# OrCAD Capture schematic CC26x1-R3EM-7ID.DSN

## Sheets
1 Mechanical: size A4; title: CC26x1-R3EM-7ID; rev: A0
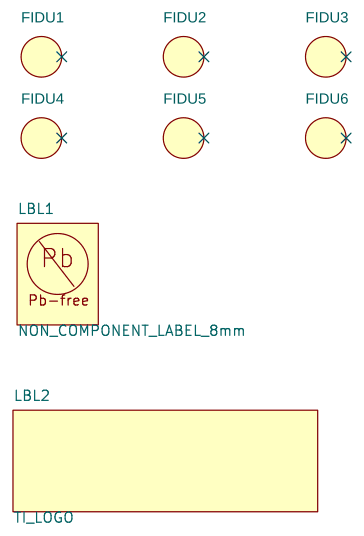
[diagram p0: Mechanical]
2 Revision
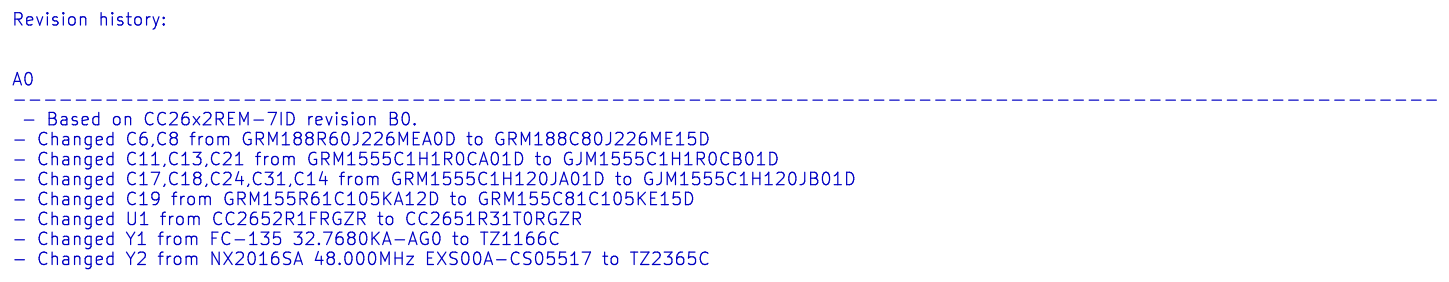
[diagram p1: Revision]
3 CC26x1-R3EM-7ID: size A3
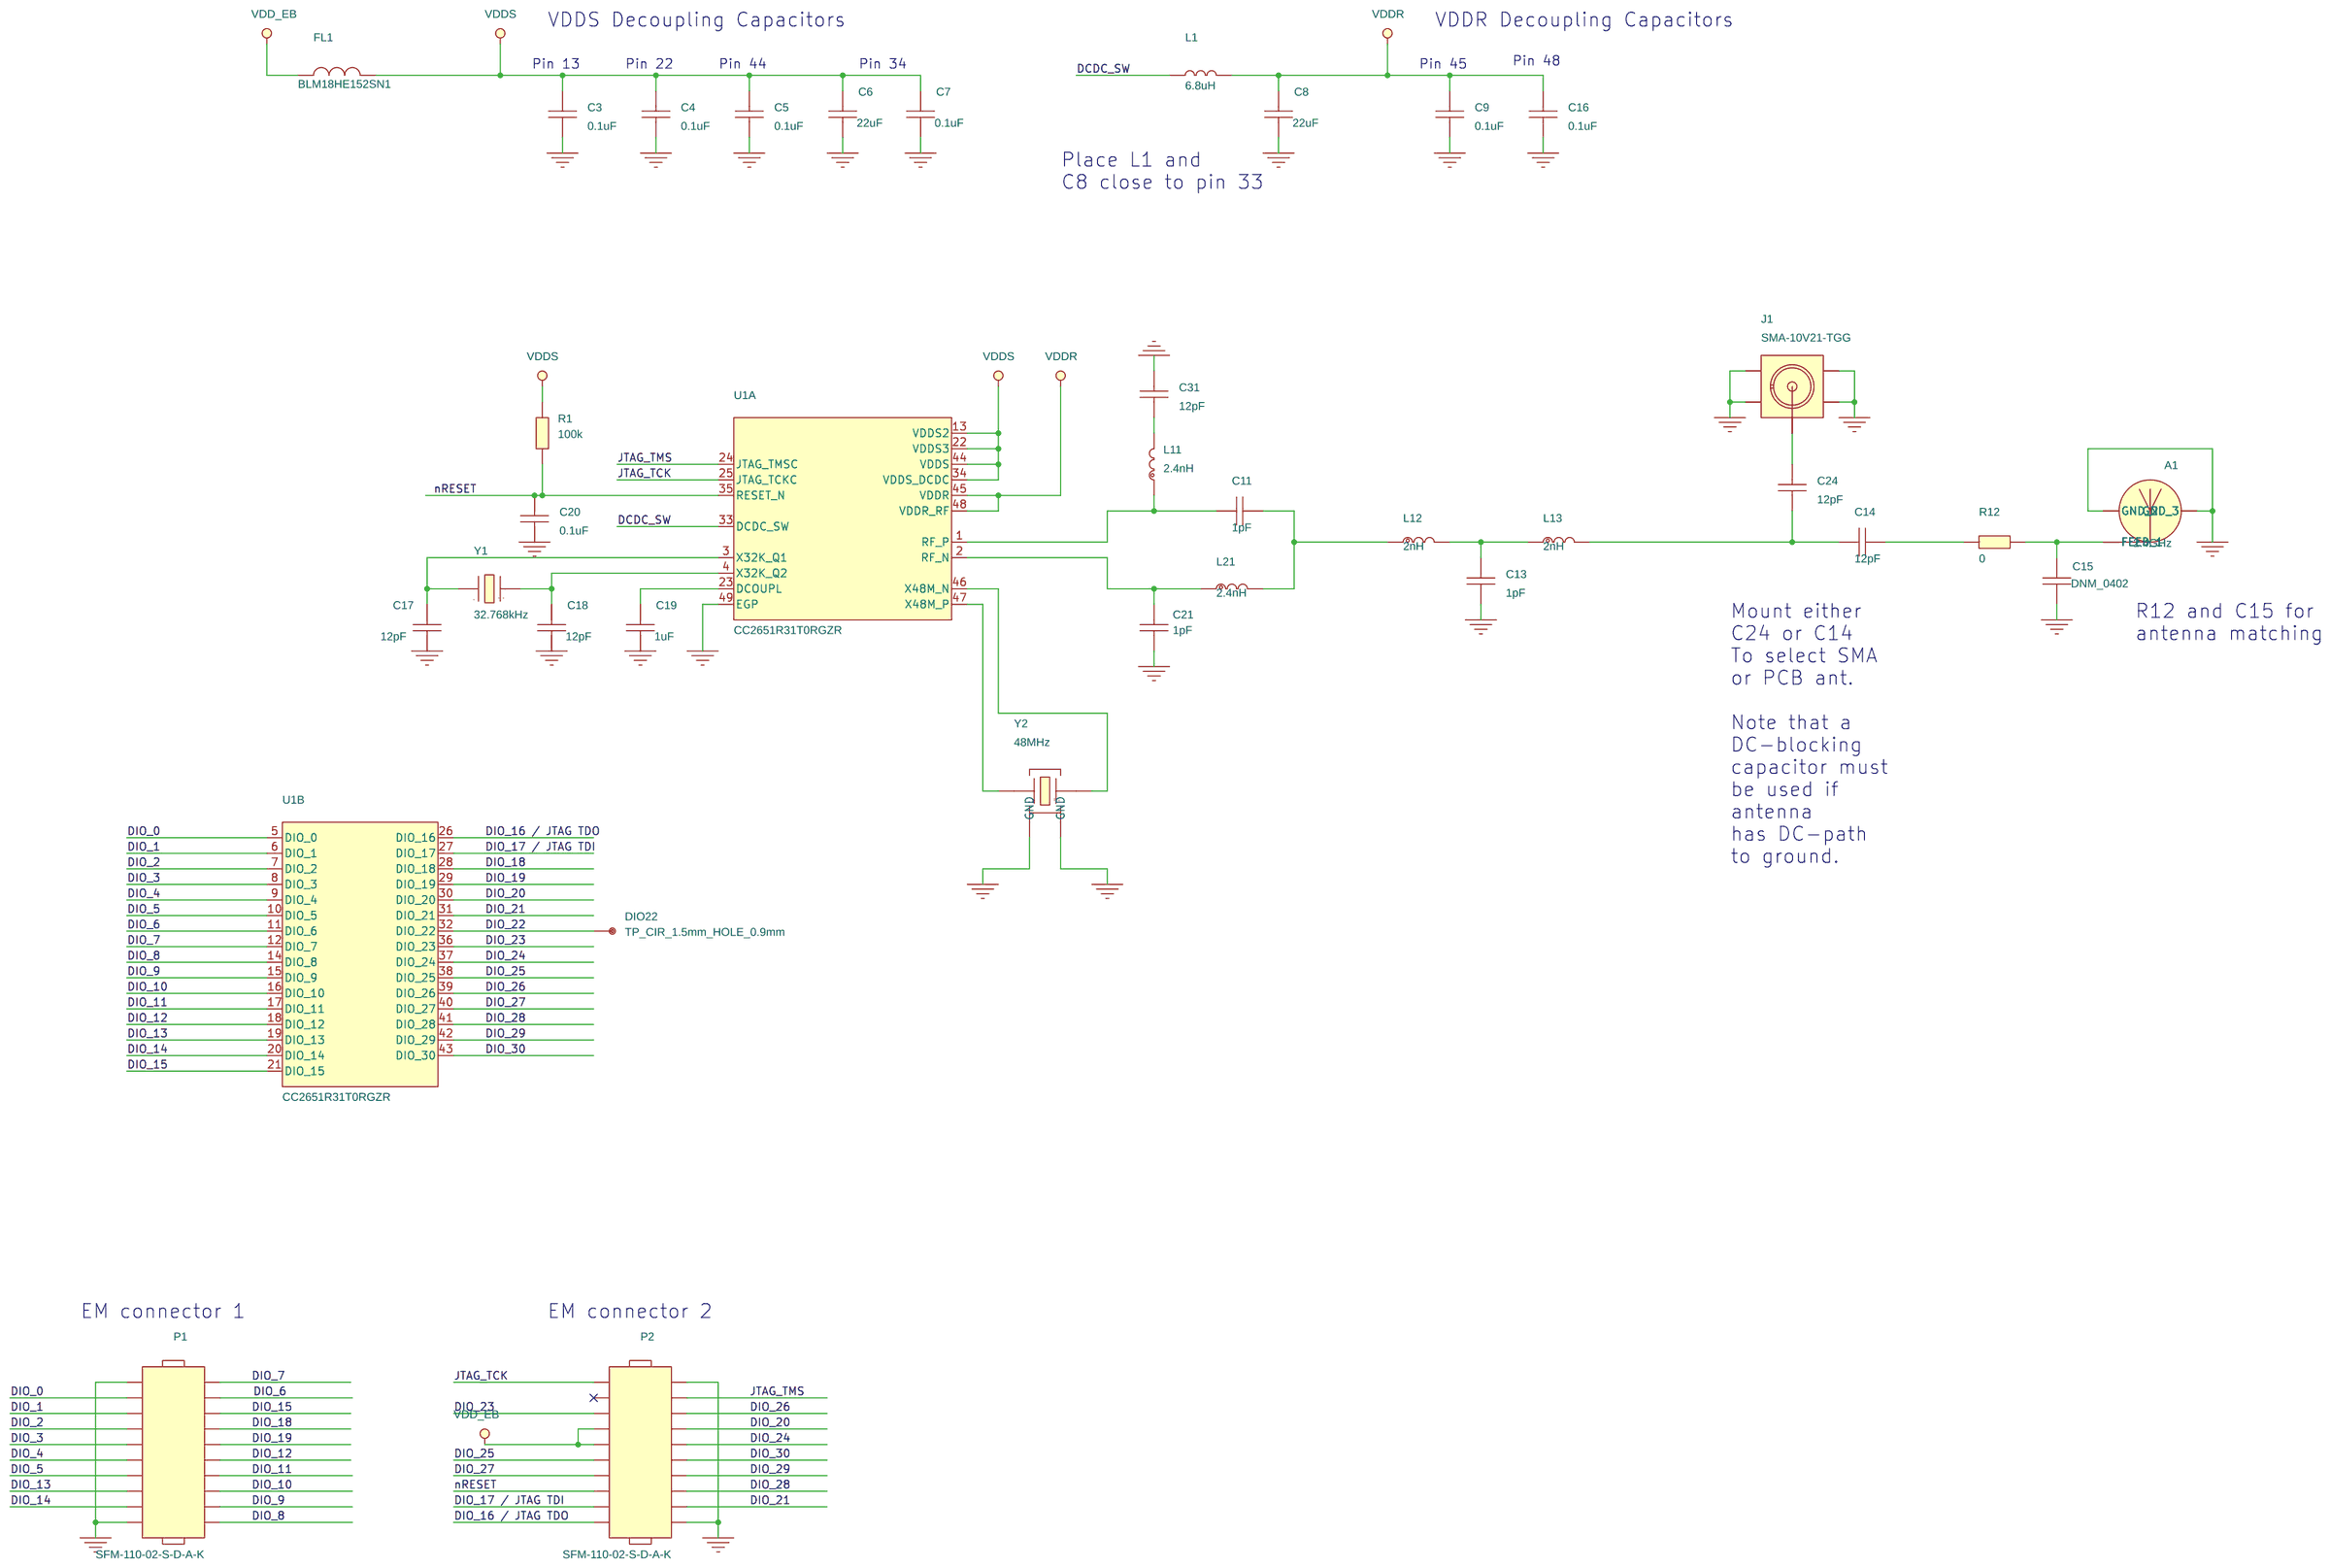
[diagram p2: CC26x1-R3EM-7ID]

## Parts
sheet CC26x1-R3EM-7ID
A1  2.4GHz  [ANTENNA_DN007AN]
C3  0.1uF  [CAPC1005X60B2N]
C4  0.1uF  [CAPC1005X60B2N]
C5  0.1uF  [CAPC1005X60B2N]
C6  22uF  [CAPC1608X100A2N]
C7  0.1uF  [CAPC1005X60B2N]
C8  22uF  [CAPC1608X100A2N]
C9  0.1uF  [CAPC1005X60B2N]
C11  1pF  [CAPC1005X60B2N]
C13  1pF  [CAPC1005X60B2N]
C14  12pF  [CAPC1005X60B2N]
C15  DNM_0402  [CAPC1005X60B2N]
C16  0.1uF  [CAPC1005X60B2N]
C17  12pF  [CAPC1005X60B2N]
C18  12pF  [CAPC1005X60B2N]
C19  1uF  [CAPC1005X60B2N]
C20  0.1uF  [CAPC1005X60B2N]
C21  1pF  [CAPC1005X60B2N]
C24  12pF  [CAPC1005X60B2N]
C31  12pF  [CAPC1005X60B2N]
DIO22  TP_CIR_1.5mm_HOLE_0.9mm  [TP150_90H]
FL1  BLM18HE152SN1  [FIL_BLM18HE152SN1DN]
J1  SMA-10V21-TGG  [HUSTSAN_SMA10V21TGGAN]
L1  6.8uH  [INDC2012X150A2N]
L11  2.4nH  [INDC1005X60D2N]
L12  2nH  [INDC1005X60D2N]
L13  2nH  [INDC1005X60D2N]
L21  2.4nH  [INDC1005X60D2N]
P1  SFM-110-02-S-D-A-K  [SAMTEC_SFM11002AN]
P2  SFM-110-02-S-D-A-K  [SAMTEC_SFM11002AN]
R1  100k  [RESC1005X40B2N]
R12  0  [RESC1005X40B2N]
U1  CC2651R31T0RGZR  [QFNFC50P700X700X100-49A2N]  (sections A,B)
Y1  32.768kHz  [XTAL_TZ1166C_A2N]
Y2  48MHz  [OSCCC200X160X50-4A2N]
sheet Mechanical
FIDU1  FIDU_1MM  [FID100X115B]
FIDU2  FIDU_1MM  [FID100X115B]
FIDU3  FIDU_1MM  [FID100X115B]
FIDU4  FIDU_1MM  [FID100X115B]
FIDU5  FIDU_1MM  [FID100X115B]
FIDU6  FIDU_1MM  [FID100X115B]
LBL1  NON_COMPONENT_LABEL_8mm  [LABEL_PB-FREE_8MM_A2N]
LBL2  TI_LOGO  [TI_LOGO_1]

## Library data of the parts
A1 = ANTENNA_DN007: ANTENNA, NON COMPONENT, 2.4GHz INVERTED F ANTENNA, NOT APPLY; Additional Datasheet URL: N/A; AutoDoc File: https://notefied-dynamic-precision.com/DB/Apps/Desktop/Item/Object.aspx?id=85542; BU Name: DYNAMIC PRECISION GDANSK; Budget Currency: N/A; Budget Price: N/A; CLASS: DISCRETE; Client Status: UNDER_REVIEW; Country of Origin: Missing Info; Datasheet URL: www.ti.com; Datasheet URL 1: http://www.ti.com/lit/an/swru120b/swru120b.pdf; Datasheet URL 2: N/A; Definied Quality: INDUSTRIAL; Esd Level: HBM 500V; Exclusive for Customers: TEXAS INSTRUMENTS NORWAY; FPLIST: ANTENNA_DN007N,ANTENNA_DN007AN,; MPN: DN007; MPN Status: ACTIVE; MSL: N/A; MTBF: N/A; MTBF Standard: N/A; Manufacturer: TEXAS INSTRUMENTS; Mass: N/A; Max Oper Temp: +85DEGC; Maximum Operating Temperature: +85DEGC; Min Oper Temp: -40DEGC; Minimum Operating Temperature: -40DEGC; Mounting Type: Not Apply; NOTE Status: PREFERRED; NOTEfied URL: https://notefied-dynamic-precision.com/NOTEfiedWebInterface/part/show?partNumber=13-00347; Notes: Custom Item; Old Footprint: ANTENNA_DN007N,ANTENNA_DN007AN; Packing Size: N/A; Packing Type: Missing Info; Part Number: 13-00347; Part Type: Mechanic|ANTENNA|NON COMPONENT; ROHS: Not Applicable; Revision: R019; RoHS Status: NOT_APPLICABLE; Status: Released; Texas Part Status: Under Review; Type: Mechanic; Vendor: TEXAS INSTRUMENTS; Vendor Part Number: DN007; Vendor Part Status: Active; WEIGHT: N/A
C3-C5 C9 C16 C20 = CAPACITOR: CAPACITOR, CERAMIC X7R, 0.1uF, 25V, -10%/+10%, -55DEGC/+125DEGC, 0402, SMD; Additional Datasheet URL: https://search.murata.co.jp/Ceramy/image/img/A01X/G101/ENG/GRM155R71E104KE14-01A.pdf; AutoDoc File: https://notefied-dynamic-precision.com/DB/Apps/Desktop/Item/Object.aspx?id=115293; BU Name: TEXAS INSTRUMENTS NORWAY; Client Status: UNDER_REVIEW; Datasheet URL: https://www.murata.com/~/media/webrenewal/support/library/catalog/products/capacitor/mlcc/c02e.ashx?la=en-gb; Datasheet URL 1: http://psearch.murata.com/capacitor/product/GRM155R71E104KE14%23.pdf; Datasheet URL 2: N/A; Dielectric Type: X7R; LifeCycle Status: ACTIVE; MPN: GRM155R70J104KA01D; MPN Status: ACTIVE; Manufacturer: MURATA; Mass: 0.0016g; Max Oper Temp: +125DEGC; Max Tol: +10%; Maximum Operating Temperature: +125DEGC; Maximum Tolerance: +10%; Min Oper Temp: -55DEGC; Min Tol: -10%; Minimum Operating Temperature: -55DEGC; Minimum Tolerance: -10%; Mounting Type: SMD; NOTE Status: PREFERRED; NOTEfied URL: https://notefied-dynamic-precision.com/NOTEfiedWebInterface/part/show?partNumber=02-07861; Old Footprint: CAPC1005X60N,0402; PCB Package: 0402; Packing Size: 10000; Packing Type: Tape & Reel; Part Number: 02-07861; Part Type: Capacitor|CERAMIC|0402|STANDARD; REACH/SVHC Compliance: Compliant; REACH/SVHC Details: SVHC List Version Jul 7, 2017; REACH/SVHC Source: REACH Declaration; REACH/SVHC Status: Unaffected; REACH/SVHC_COMPLIANCE: COMPLIANT; REACH/SVHC_DETAILS: SVHC LIST VERSION Jun 20, 2016; REACH/SVHC_SOURCE: REACH DECLARATION; REACH/SVHC_STATUS: UNAFFECTED; ROHS: Compliant; Rated Voltage: 25V; Revision: R014; RoHS Status: ROHS_COMPLIANT; Rtd Voltage: 25V; Status: Released; Texas Part Status: Under Review; Type: Capacitor; Vendor: MURATA; Vendor Part Number: GRM155R71E104KE14D; Vendor Part Status: NRND; WEIGHT: 0.0016g
C6 C8 = CAPACITOR: CAPACITOR, CERAMIC X6S, 22uF, 6.3V, -20%/+20%, -55DEGC/+105DEGC, 0603, SMD; ALT_SYMBOLS: CAPC1608X100A2L,CAPC1608X100A2M; Additional Datasheet URL: https://search.murata.co.jp/Ceramy/image/img/A01X/G101/ENG/GRM188C80J226ME15-02A.pdf; AutoDoc File: https://notefied-dynamic-precision.com/DB/Apps/Desktop/Item/Object.aspx?id=104385; BU Name: DYNAMIC PRECISION GDANSK; Budget Currency: EUR; Budget Price: 0.062; Budgetary Price: 0.07648 USD; Client Status: UNDER_REVIEW; Datasheet URL: https://www.murata.com/-/media/webrenewal/support/library/catalog/products/capacitor/mlcc/c02e.ashx; Datasheet URL 1: http://psearch.murata.com/capacitor/product/GRM188R60J226MEA0%23.pdf; Datasheet URL 2: N/A; Definied Quality: INDUSTRIAL; Dielectric Type: X6S; Esd Level: N/A; Lead Time: 15; MPN: GRM188R60J106ME47D; MPN Status: NRND; MSL: 1; MTBF: N/A; MTBF Standard: N/A; Manufacturer: MURATA; Mass: 0.0091g; Max Oper Temp: +85DEGC; Max Tol: +20%; Maximum Operating Temperature: +105DEGC; Maximum Tolerance: +20%; Min Oper Temp: -55DEGC; Min Tol: -20%; Minimum Operating Temperature: -55DEGC; Minimum Tolerance: -20%; Mounting Type: SMD; NOTE Status: PREFERRED; NOTEfied URL: https://notefied-dynamic-precision.com/NOTEfiedWebInterface/part/show?partNumber=02-09737; Old Footprint: CAPC1608X90N; PCB Package: 0603; Packing Size: 4000; Packing Type: Tape & Reel; Part Number: 02-09737; Part Type: Capacitor|CERAMIC|0603|STANDARD; REACH/SVHC Compliance: Compliant; REACH/SVHC Details: SVHC List Version Jan 16, 2020; REACH/SVHC Source: REACH Declaration; REACH/SVHC Status: Unaffected; REACH/SVHC_COMPLIANCE: COMPLIANT; REACH/SVHC_DETAILS: SVHC LIST VERSION Dec 17, 2015; REACH/SVHC_SOURCE: REACH DECLARATION; REACH/SVHC_STATUS: UNAFFECTED; ROHS: Compliant; Rated Current: N/A; Rated Voltage: 6.3V; Revision: R001; RoHS Status: ROHS_COMPLIANT; Rtd Voltage: 6.3V; Status: Released; Texas Part Status: Under Review; Type: Capacitor; Vendor: MURATA; Vendor Part Number: GRM188C80J226ME15D; Vendor Part Status: Active; WEIGHT: 0.0091g
C7 = CAPACITOR: CAPACITOR, CERAMIC X7R, 0.1uF, 25V, -10%/+10%, -55DEGC/+125DEGC, 0402, SMD; Additional Datasheet URL: https://search.murata.co.jp/Ceramy/image/img/A01X/G101/ENG/GRM155R71E104KE14-01A.pdf; AutoDoc File: https://notefied-dynamic-precision.com/DB/Apps/Desktop/Item/Object.aspx?id=115293; BU Name: TEXAS INSTRUMENTS NORWAY; Cage Code: C0151; Client Status: UNDER_REVIEW; Datasheet URL: https://www.murata.com/~/media/webrenewal/support/library/catalog/products/capacitor/mlcc/c02e.ashx?la=en-gb; Datasheet URL 1: http://psearch.murata.com/capacitor/product/GRM155R71E104KE14%23.pdf; Datasheet URL 2: N/A; Dielectric Type: X7R; MPN: GRM188R71E104KA01D; MPN Status: ACTIVE; Manufacturer: MURATA; Mass: 0.0016g; Max Oper Temp: +125DEGC; Max Tol: +10%; Maximum Operating Temperature: +125DEGC; Maximum Tolerance: +10%; Min Oper Temp: -55DEGC; Min Tol: -10%; Minimum Operating Temperature: -55DEGC; Minimum Tolerance: -10%; Mounting Type: SMD; NOTE Status: PREFERRED; NOTEfied URL: https://notefied-dynamic-precision.com/NOTEfiedWebInterface/part/show?partNumber=02-07861; Old Footprint: CAPC1608X90N,0603; PCB Package: 0402; Packing Size: 10000; Packing Type: Tape & Reel; Part Number: 02-07861; Part Type: Capacitor|CERAMIC|0402|STANDARD; REACH/SVHC Compliance: Compliant; REACH/SVHC Details: SVHC List Version Jul 7, 2017; REACH/SVHC Source: REACH Declaration; REACH/SVHC Status: Unaffected; REACH/SVHC_COMPLIANCE: COMPLIANT; REACH/SVHC_DETAILS: SVHC LIST VERSION Jun 20, 2016; REACH/SVHC_SOURCE: REACH DECLARATION; REACH/SVHC_STATUS: UNAFFECTED; ROHS: Compliant; Rated Voltage: 25V; Revision: R014; RoHS Status: ROHS_COMPLIANT; Rtd Voltage: 25V; Status: Released; Texas Part Status: Under Review; Type: Capacitor; Vendor: MURATA; Vendor Part Number: GRM155R71E104KE14D; Vendor Part Status: NRND; WEIGHT: 0.0016g
C11 C13 C21 = CAPACITOR: CAPACITOR, CERAMIC C0G/NP0, 1pF, 50V, -0.25pF/+0.25pF, -55DEGC/+125DEGC, 0402, SMD; Additional Datasheet URL: https://search.murata.co.jp/Ceramy/image/img/A01X/G101/ENG/GJM1555C1H1R0CB01-01.pdf; AutoDoc File: https://notefied-dynamic-precision.com/DB/Apps/Desktop/Item/Object.aspx?id=113355; BU Name: TEXAS INSTRUMENTS NORWAY; Budget Currency: EUR; Budget Price: 0.006; Datasheet URL: https://www.murata.com/-/media/webrenewal/support/library/catalog/products/capacitor/mlcc/c02e.ashx; Datasheet URL 1: http://psearch.murata.com/capacitor/product/GRM1555C1H1R0CA01%23.pdf; Datasheet URL 2: http://search.murata.co.jp/Ceramy/image/img/w_hinm/L0005E.pdf; Dielectric Type: C0G/NP0; MPN: GRM1555C1H1R0CA01D; MPN Status: ACTIVE; Manufacturer: MURATA; Mass: 0.0016g; Max Oper Temp: +125DEGC; Max Tol: +0.25pF; Maximum Operating Temperature: +125DEGC; Maximum Tolerance: +0.25pF; Min Oper Temp: -55DEGC; Min Tol: -0.25pF; Minimum Operating Temperature: -55DEGC; Minimum Tolerance: -0.25pF; Mounting Type: SMD; NOTE Status: PREFERRED; NOTEfied URL: https://notefied-dynamic-precision.com/NOTEfiedWebInterface/part/show?partNumber=02-09706; Old Footprint: CAPC1005X60N; PCB Package: 0402; Packing Size: 10000; Packing Type: Tape & Reel; Part Number: 02-09706; Part Type: Capacitor|CERAMIC|0402|STANDARD; REACH/SVHC Compliance: Compliant; REACH/SVHC Details: SVHC List Version Jan 16, 2020; REACH/SVHC Source: REACH Declaration; REACH/SVHC Status: Unaffected; REACH/SVHC_COMPLIANCE: COMPLIANT; REACH/SVHC_DETAILS: SVHC LIST VERSION Dec 17, 2015; REACH/SVHC_SOURCE: REACH DECLARATION; REACH/SVHC_STATUS: UNAFFECTED; ROHS: Compliant; Rated Voltage: 50V; Revision: R002; RoHS Status: ROHS_COMPLIANT; Rtd Voltage: 50V; Status: Released; Texas Part Status: Under Review; Type: Capacitor; Vendor: MURATA; Vendor Part Number: GJM1555C1H1R0CB01D; Vendor Part Status: Active; WEIGHT: 0.0016g
C14 C24 = CAPACITOR: CAPACITOR, CERAMIC C0G/NP0, 12pF, 50V, -5%/+5%, -55DEGC/+125DEGC, 0402, SMD; Additional Datasheet URL: https://search.murata.co.jp/Ceramy/image/img/A01X/G101/ENG/GJM1555C1H120JB01-01.pdf; AutoDoc File: https://notefied-dynamic-precision.com/DB/Apps/Desktop/Item/Object.aspx?id=113345; BU Name: TEXAS INSTRUMENTS NORWAY; Budget Currency: EUR; Budget Price: 0.007; Datasheet URL: https://www.murata.com/-/media/webrenewal/support/library/catalog/products/capacitor/mlcc/c02e.ashx; Datasheet URL 1: http://psearch.murata.com/capacitor/product/GRM1555C1H120JA01%23.pdf; Datasheet URL 2: http://search.murata.co.jp/Ceramy/image/img/w_hinm/L0005E.pdf; Dielectric Type: C0G/NP0; MPN: GRM1555C1H120JA01D; MPN Status: ACTIVE; Manufacturer: MURATA; Mass: 0.0016g; Max Oper Temp: +125DEGC; Max Tol: +5%; Maximum Operating Temperature: +125DEGC; Maximum Tolerance: +5%; Min Oper Temp: -55DEGC; Min Tol: -5%; Minimum Operating Temperature: -55DEGC; Minimum Tolerance: -5%; Mounting Type: SMD; NOTE Status: PREFERRED; NOTEfied URL: https://notefied-dynamic-precision.com/NOTEfiedWebInterface/part/show?partNumber=02-09704; Old Footprint: CAPC1005X60N; PCB Package: 0402; Packing Size: 10000; Packing Type: Tape & Reel; Part Number: 02-09704; Part Type: Capacitor|CERAMIC|0402|STANDARD; REACH/SVHC Compliance: Compliant; REACH/SVHC Details: SVHC List Version Jan 16, 2020; REACH/SVHC Source: REACH Declaration; REACH/SVHC Status: Unaffected; REACH/SVHC_COMPLIANCE: COMPLIANT; REACH/SVHC_DETAILS: SVHC LIST VERSION Dec 17, 2015; REACH/SVHC_SOURCE: REACH DECLARATION; REACH/SVHC_STATUS: UNAFFECTED; ROHS: Compliant; Rated Voltage: 50V; Revision: R002; RoHS Status: ROHS_COMPLIANT; Rtd Voltage: 50V; Status: Released; Texas Part Status: Under Review; Type: Capacitor; Vendor: MURATA; Vendor Part Number: GJM1555C1H120JB01D; Vendor Part Status: Active; WEIGHT: 0.0016g
C15 = CAPACITOR: CAPACITOR, CERAMIC, TBD, 0402, SMD, DNM; Additional Datasheet URL: N/A; AutoDoc File: https://notefied-dynamic-precision.com/DB/Apps/Desktop/Item/Object.aspx?id=113344; BU Name: TEXAS INSTRUMENTS NORWAY; Country of Origin: Missing Info; Datasheet URL: N/A; Datasheet URL 1: N/A; Datasheet URL 2: N/A; Dielectric Type: MISSING-INFO; Exclusive for Customers: TEXAS INSTRUMENTS NORWAY; MPN: CAPACITOR_0402_DNM_N/A_M; MPN Status: ACTIVE; Manufacturer: Manufacturer selection; Mass: N/A; Max Oper Temp: +125DEGC; Maximum Operating Temperature: +125DEGC; Min Oper Temp: -55DEGC; Minimum Operating Temperature: -55DEGC; Mounting Type: SMD; NOTE Status: PREFERRED; NOTEfied URL: https://notefied-dynamic-precision.com/NOTEfiedWebInterface/part/show?partNumber=02-07616; Notes: Standard item: Duplicate Reason: custom footprint for TEXAS INSTRUMENTS NORWAY.; Old Footprint: CAPC1005X60N; PCB Package: 0402; Part Number: 02-07616; Part Type: Capacitor|CERAMIC|0402|STANDARD; ROHS: Compliant; Revision: R014; RoHS Status: ROHS_COMPLIANT; Status: Released; Texas Part Status: Under Review; Type: Capacitor; Vendor: MANUFACTURER SELECTION; Vendor Part Number: CAPACITOR_TBD_0402_DNM; Vendor Part Status: Active; Weight: N/A
C17 C18 = CAPACITOR: CAPACITOR, CERAMIC C0G/NP0, 12pF, 50V, -5%/+5%, -55DEGC/+125DEGC, 0402, SMD; Additional Datasheet URL: https://search.murata.co.jp/Ceramy/image/img/A01X/G101/ENG/GJM1555C1H120JB01-01.pdf; AutoDoc File: https://notefied-dynamic-precision.com/DB/Apps/Desktop/Item/Object.aspx?id=113345; BU Name: TEXAS INSTRUMENTS NORWAY; Budget Currency: EUR; Budget Price: 0.007; Datasheet URL: https://www.murata.com/-/media/webrenewal/support/library/catalog/products/capacitor/mlcc/c02e.ashx; Datasheet URL 1: http://psearch.murata.com/capacitor/product/GRM1555C1H120JA01%23.pdf; Datasheet URL 2: http://search.murata.co.jp/Ceramy/image/img/w_hinm/L0005E.pdf; Definied Quality: INDUSTRIAL; Dielectric Type: C0G/NP0; Esd Level: N/A; LifeCycle Status: ACTIVE; MPN: CAPACITOR_0402_12pF_C0G/NP0_M_+/-5%_50V; MPN Status: ACTIVE; MSL: N/A; MTBF: N/A; MTBF Standard: N/A; Manufacturer: MANUFACTURER SELECTION; Mass: 0.0016g; Max Oper Temp: +125DEGC; Max Tol: +5%; Maximum Operating Temperature: +125DEGC; Maximum Tolerance: +5%; Min Oper Temp: -55DEGC; Min Tol: -5%; Minimum Operating Temperature: -55DEGC; Minimum Tolerance: -5%; Mounting Type: SMD; NOTE Status: PREFERRED; NOTEfied URL: https://notefied-dynamic-precision.com/NOTEfiedWebInterface/part/show?partNumber=02-09704; Old Footprint: CAPC1005X60N; PCB Package: 0402; Packing Size: 10000; Packing Type: Tape & Reel; Part Number: 02-09704; Part Type: Capacitor|CERAMIC|0402|STANDARD; REACH/SVHC Compliance: Compliant; REACH/SVHC Details: SVHC List Version Jan 16, 2020; REACH/SVHC Source: REACH Declaration; REACH/SVHC Status: Unaffected; REACH/SVHC_COMPLIANCE: COMPLIANT; REACH/SVHC_DETAILS: SVHC LIST VERSION Dec 17, 2015; REACH/SVHC_SOURCE: REACH DECLARATION; REACH/SVHC_STATUS: UNAFFECTED; ROHS: Compliant; Rated Voltage: 50V; Revision: R002; RoHS Status: ROHS_COMPLIANT; Rtd Voltage: 50V; Status: Released; Texas Part Status: Under Review; Type: Capacitor; Vendor: MURATA; Vendor Part Number: GJM1555C1H120JB01D; Vendor Part Status: Active; WEIGHT: 0.0016g
C19 = CAPACITOR: CAPACITOR, CERAMIC X6S, 1uF, 16V, -10%/+10%, -55DEGC/+105DEGC, 0402, SMD; Additional Datasheet URL: https://search.murata.co.jp/Ceramy/image/img/A01X/G101/ENG/GRM155C81C105KE15-01A.pdf; AutoDoc File: https://notefied-dynamic-precision.com/DB/Apps/Desktop/Item/Object.aspx?id=115295; BU Name: TEXAS INSTRUMENTS NORWAY; Client Status: UNDER_REVIEW; Datasheet URL: https://www.murata.com/-/media/webrenewal/support/library/catalog/products/capacitor/mlcc/c02e.ashx; Datasheet URL 1: http://psearch.murata.com/capacitor/product/GRM155R61C105KA12%23.pdf; Datasheet URL 2: N/A; Definied Quality: INDUSTRIAL; Dielectric Type: X6S; Esd Level: N/A; MPN: GRM155R61A105KE15D; MPN Status: ACTIVE; MSL: 1; MTBF: N/A; MTBF Standard: N/A; Manufacturer: MURATA; Mass: 0.0016g; Max Oper Temp: +85DEGC; Max Tol: +10%; Maximum Operating Temperature: +105DEGC; Maximum Tolerance: +10%; Min Oper Temp: -55DEGC; Min Tol: -10%; Minimum Operating Temperature: -55DEGC; Minimum Tolerance: -10%; Mounting Type: SMD; NOTE Status: PREFERRED; NOTEfied URL: https://notefied-dynamic-precision.com/NOTEfiedWebInterface/part/show?partNumber=02-09721; Old Footprint: CAPC1005X60N,0402; PCB Package: 0402; Packing Size: 10000; Packing Type: Tape & Reel; Part Number: 02-09721; Part Type: Capacitor|CERAMIC|0402|STANDARD; REACH/SVHC Compliance: Compliant; REACH/SVHC Details: SVHC List Version Jan 16, 2020; REACH/SVHC Source: REACH Declaration; REACH/SVHC Status: Unaffected; REACH/SVHC_COMPLIANCE: COMPLIANT; REACH/SVHC_DETAILS: SVHC LIST VERSION Jun 20, 2016; REACH/SVHC_SOURCE: REACH DECLARATION; REACH/SVHC_STATUS: UNAFFECTED; ROHS: Compliant; Rated Voltage: 16V; Revision: R002; RoHS Status: ROHS_COMPLIANT; Rtd Voltage: 16V; Status: Released; Texas Part Status: Under Review; Type: Capacitor; Vendor: MURATA; Vendor Part Number: GRM155C81C105KE15D; Vendor Part Status: Active; WEIGHT: 0.0016g
C31 = CAPACITOR: CAPACITOR, CERAMIC C0G/NP0, 12pF, 50V, -5%/+5%, -55DEGC/+125DEGC, 0402, SMD; Additional Datasheet URL: https://search.murata.co.jp/Ceramy/image/img/A01X/G101/ENG/GJM1555C1H120JB01-01.pdf; AutoDoc File: https://notefied-dynamic-precision.com/DB/Apps/Desktop/Item/Object.aspx?id=113345; BU Name: TEXAS INSTRUMENTS NORWAY; Budget Currency: EUR; Budget Price: 0.007; Datasheet URL: https://www.murata.com/-/media/webrenewal/support/library/catalog/products/capacitor/mlcc/c02e.ashx; Datasheet URL 1: http://psearch.murata.com/capacitor/product/GRM1555C1H120JA01%23.pdf; Datasheet URL 2: http://search.murata.co.jp/Ceramy/image/img/w_hinm/L0005E.pdf; Dielectric Type: C0G/NP0; MPN: GRM1555C1H6R8CA01D; MPN Status: ACTIVE; Manufacturer: MURATA; Mass: 0.0016g; Max Oper Temp: +125DEGC; Max Tol: +5%; Maximum Operating Temperature: +125DEGC; Maximum Tolerance: +5%; Min Oper Temp: -55DEGC; Min Tol: -5%; Minimum Operating Temperature: -55DEGC; Minimum Tolerance: -5%; Mounting Type: SMD; NOTE Status: PREFERRED; NOTEfied URL: https://notefied-dynamic-precision.com/NOTEfiedWebInterface/part/show?partNumber=02-09704; Old Footprint: CAPC1005X60N; PCB Package: 0402; Packing Size: 10000; Packing Type: Tape & Reel; Part Number: 02-09704; Part Type: Capacitor|CERAMIC|0402|STANDARD; REACH/SVHC Compliance: Compliant; REACH/SVHC Details: SVHC List Version Jan 16, 2020; REACH/SVHC Source: REACH Declaration; REACH/SVHC Status: Unaffected; REACH/SVHC_COMPLIANCE: COMPLIANT; REACH/SVHC_DETAILS: SVHC LIST VERSION Dec 17, 2015; REACH/SVHC_SOURCE: REACH DECLARATION; REACH/SVHC_STATUS: UNAFFECTED; ROHS: Compliant; Rated Voltage: 50V; Revision: R002; RoHS Status: ROHS_COMPLIANT; Rtd Voltage: 50V; Status: Released; Texas Part Status: Under Review; Type: Capacitor; Vendor: MURATA; Vendor Part Number: GJM1555C1H120JB01D; Vendor Part Status: Active; WEIGHT: 0.0016g
DIO22 = TEST_POINT: NON COMPONENT, TEST POINT, CIRCULAR 1.5mm, HOLE 0.9mm, PTH; Additional Datasheet URL: N/A; AutoDoc File: https://notefied-dynamic-precision.com/DB/Apps/Desktop/Item/Object.aspx?id=84966; BU Name: DYNAMIC PRECISION GDANSK; CLASS: IO; Country of Origin: Missing Info; Datasheet URL: N/A; FPLIST: TP150_90H,; Mass: N/A; Mounting Type: PTH; NOTEfied URL: https://notefied-dynamic-precision.com/NOTEfiedWebInterface/part/show?partNumber=19-00299; Packing Size: N/A; Packing Type: Missing Info; Part Number: 19-00299; Part Type: Non Component|TEST POINT; ROHS: Not Applicable; Revision: R018; Status: Released; Texas Part Status: Under Review; Type: Non Component; Vendor: NON_COMPONENT; Vendor Part Status: Active
FL1 = FILTER_2PIN: FILTER, EMI, FERRITE BEAD, 1500@100MHz, -25%/+25%, -55DEGC/+125DEGC, 0603, SMD; ALT_SYMBOLS: FIL_BLM18HE152SN1DL,FIL_BLM18HE152SN1DM; Additional Datasheet URL: https://www.murata.com/en-eu/products/productdata/8796741599262/ENFA0004.pdf?1441769419000; AutoDoc File: https://notefied-dynamic-precision.com/DB/Apps/Desktop/Item/Object.aspx?id=85575; BU Name: DYNAMIC PRECISION GDANSK; Budget Currency: EUR; Budget Price: 0.065; Budgetary Price: 0.065 EUR; CLASS: IC; Client Status: UNDER_REVIEW; Country of Origin: Japan,Singapore,Thailand; Datasheet URL: https://www.murata.com/~/media/webrenewal/support/library/catalog/products/emc/emifil/c31e.ashx; Datasheet URL 1: http://search.murata.co.jp/Ceramy/image/img/PDF/ENG/L0110S0101BLM18H.pdf; Datasheet URL 2: http://search.murata.co.jp/Ceramy/image/img/w_hinm/L0110E.pdf; Frequency: 100MHz; Impedance: 1500; Inductance: N/A; Lead Time: 9; MPN: BLM18HE152SN1D; MPN Status: ACTIVE; Manufacturer: MURATA; Mass: 0.006g; Max Oper Temp: +125DEGC; Max Tol: +25%; Maximum Operating Temperature: +125DEGC; Maximum Tolerance: +25%; Min Oper Temp: -55DEGC; Min Tol: -25%; Minimum Operating Temperature: -55DEGC; Minimum Tolerance: -25%; Mounting Type: SMD; NOTE Status: PREFERRED; NOTEfied URL: https://notefied-dynamic-precision.com/NOTEfiedWebInterface/part/show?partNumber=04-00470; PCB Package: 0603; Packing Size: 4000; Packing Type: Tape & Reel; Part Number: 04-00470; Part Type: Filter|EMI|FERRITE BEAD|0603; REACH/SVHC Compliance: Compliant; REACH/SVHC Details: SVHC List Version Jul 7, 2017; REACH/SVHC Source: REACH Declaration; REACH/SVHC Status: Unaffected; REACH/SVHC_COMPLIANCE: COMPLIANT; REACH/SVHC_DETAILS: SVHC LIST VERSION Dec 17, 2015; REACH/SVHC_SOURCE: REACH DECLARATION; REACH/SVHC_STATUS: UNAFFECTED; ROHS: Compliant; Rated Current: 0.5A; Rated Voltage: N/A; Revision: R015; RoHS Status: ROHS_COMPLIANT; Rtd Current: 0.5A; Rtd Voltage: N/A; Status: Released; Texas Part Status: Under Review; Type: Filter; Vendor: MURATA; Vendor Part Number: BLM18HE152SN1D; Vendor Part Status: Active; WEIGHT: 0.006g
J1 = CONN_COAX_1+4: CONNECTOR, COAX, RF, FEMALE, STRAIGHT, 1 PIN, SMD; ALT_SYMBOLS: HUSTSAN_SMA10V21TGGL,HUSTSAN_SMA10V21TGGM; Additional Datasheet URL: http://www.hustsan.com.tw/cgi-bin/productfn/pdt_detail_lst.pl?ProdID=143; AutoDoc File: https://notefied-dynamic-precision.com/DB/Apps/Desktop/Item/Object.aspx?id=84956; BU Name: DYNAMIC PRECISION GDANSK; Budget Currency: N/A; Budget Price: N/A; CLASS: IO; Client Status: UNDER_REVIEW; Country of Origin: Taiwan; Datasheet URL: http://www.hustsan.com.tw/uploaddir/product/SMA-10V21.pdf; Datasheet URL 1: http://www.hustsan.com.tw/uploaddir/product/SMA-10V21.pdf; Datasheet URL 2: http://www.hustsan.com.tw/cgi-bin/productfn/pdt_detail_lst.pl?ProdID=143; FPLIST: HUSTSAN_SMA10V21TGGAN,HUSTSAN_SMA10V21TGGN; MPN Status: ACTIVE; MSL: N/A; Manufacturer: HUS-TSAN; Mass: N/A; Mounting Type: SMD; NOTE Status: PREFERRED; NOTEfied URL: https://notefied-dynamic-precision.com/NOTEfiedWebInterface/part/show?partNumber=06-02188; No Of Pos: 1; Number of Positions: 1; Old Footprint: HUSTSAN_SMA10V21TGGAN,HUSTSAN_SMA10V21TGGN; Packing Size: 350; Packing Type: Tape & Reel; Part Number: 06-02188; Part Type: Connector|COAX|RF; REACH/SVHC Compliance: Compliant; REACH/SVHC Details: SVHC List Version Jun 20, 2016; REACH/SVHC Source: REACH Declaration; REACH/SVHC Status: Unaffected; ROHS: Compliant; Revision: R014; RoHS Status: ROHS_COMPLIANT; Status: Released; Texas Part Status: Under Review; Type: Connector; Vendor: HUS-TSAN; Vendor Part Status: Active; WEIGHT: N/A
L1 = INDUCTOR: INDUCTOR, STANDARD, FERRITE CORE, 6.8uH, -20%/+20%, 0.11A, -55DEGC/+125DEGC, 0805, SMD; ALT_SYMBOLS: INDC2012X150A2L,INDC2012X150A2M; Additional Datasheet URL: https://product.tdk.com/en/search/inductor/inductor/smd/info?part_no=MLZ2012N6R8LT000; AutoDoc File: https://notefied-dynamic-precision.com/DB/Apps/Desktop/Item/Object.aspx?id=102853; BU Name: DYNAMIC PRECISION GDANSK; Budget Currency: EUR; Budget Price: 0.059; Budgetary Price: 0.045 USD; CLASS: DISCRETE; Client Status: UNDER_REVIEW; Core Material: FERRITE; Country of Origin: Missing Info; Datasheet URL: http://product.tdk.com/info/en/catalog/datasheets/inductor_commercial_decoupling_mlz2012_en.pdf; Datasheet URL 1: https://product.tdk.com/en/search/inductor/inductor/smd/info?part_no=MLZ2012N6R8LT000; Datasheet URL 2: http://product.tdk.com/info/en/catalog/datasheets/inductor_commercial_decoupling_mlz2012_en.pdf; Lead Time: 10; MPN: CKS2125100M-T; MPN Status: ACTIVE; Manufacturer: TAIYO YUDEN; Mass: 0.01g; Max Oper Temp: +125DEGC; Max Tol: +20%; Maximum Operating Temperature: +125DEGC; Maximum Tolerance: +20%; Min Oper Temp: -55DEGC; Min Tol: -20%; Minimum Operating Temperature: -55DEGC; Minimum Tolerance: -20%; Mounting Type: SMD; NOTE Status: PREFERRED; NOTEfied URL: https://notefied-dynamic-precision.com/NOTEfiedWebInterface/part/show?partNumber=03-07266; Old Footprint: INDC2012X150N; PCB Package: 0805; Packing Size: 4000; Packing Type: Tape & Reel; Part Number: 03-07266; Part Type: Inductor|STANDARD|CHIP|0805; REACH/SVHC Compliance: Compliant; REACH/SVHC Details: SVHC List Version Jan 12, 2017; REACH/SVHC Source: REACH Declaration; REACH/SVHC Status: Unaffected; REACH/SVHC_COMPLIANCE: COMPLIANT; REACH/SVHC_DETAILS: SVHC LIST VERSION Dec 17, 2015; REACH/SVHC_SOURCE: REACH DECLARATION; REACH/SVHC_STATUS: UNAFFECTED; ROHS: Compliant; Resistance: 0.25; Revision: R014; RoHS Status: ROHS_COMPLIANT; Rtd Current: 1.1A; Status: Released; Texas Part Status: Under Review; Type: Inductor; Vendor: TDK; Vendor Part Number: MLZ2012N6R8LT000; Vendor Part Status: Active; Weight: 0.01g
L11 L21 = INDUCTOR_HOR_1_2: INDUCTOR, RF, CHIP, NON-MAGNETIC CORE, 2.4nH, -0.3nH/+0.3nH, 0.3A, -55DEGC/+125DEGC, 0402, SMD; Additional Datasheet URL: https://search.murata.co.jp/Ceramy/image/img/P02/JELF243B-0010.pdf; AutoDoc File: https://notefied-dynamic-precision.com/DB/Apps/Desktop/Item/Object.aspx?id=113363; BU Name: TEXAS INSTRUMENTS NORWAY; Budget Currency: EUR; Budget Price: 0.031; Budgetary Price: 0.031 EUR; Client Status: UNDER_REVIEW; Core Material: NON-MAGNETIC; Country of Origin: Japan,Singapore; Datasheet URL: https://www.murata.com/~/media/webrenewal/support/library/catalog/products/inductor/chip/o05e.ashx?la=en-gb; Datasheet URL 1: http://psearch.murata.com/inductor/product/LQG15HS2N4S02%23.pdf; Datasheet URL 2: http://www.murata.com/~/media/webrenewal/support/library/catalog/products/inductor/chip/o05e.ashx; Exclusive for Customers: TEXAS INSTRUMENTS NORWAY; Frequency: 6GHz; Lead Time: 9; Mass: 0.001g; Max Oper Temp: +125DEGC; Max Tol: +0.3nH; Maximum Operating Temperature: +125DEGC; Maximum Tolerance: +0.3nH; Min Oper Temp: -55DEGC; Min Tol: -0.3nH; Minimum Operating Temperature: -55DEGC; Minimum Tolerance: -0.3nH; Mounting Type: SMD; NOTEfied URL: https://notefied-dynamic-precision.com/NOTEfiedWebInterface/part/show?partNumber=03-07526; Notes: Standard item: Duplicate Reason: custom footprint for TEXAS INSTRUMENTS NORWAY.; PCB Package: 0402; Packing Size: 10000; Packing Type: Tape & Reel; Part Number: 03-07526; Part Type: Inductor|RF|CHIP|0402; REACH/SVHC Compliance: Compliant; REACH/SVHC Details: SVHC List Version Jul 7, 2017; REACH/SVHC Source: REACH Declaration; REACH/SVHC Status: Unaffected; REACH/SVHC_COMPLIANCE: COMPLIANT; REACH/SVHC_DETAILS: SVHC LIST VERSION Dec 17, 2015; REACH/SVHC_SOURCE: REACH DECLARATION; REACH/SVHC_STATUS: UNAFFECTED; ROHS: Compliant; Revision: R019; RoHS Status: ROHS_COMPLIANT; Rtd Current: 0.3A; Status: Released; Texas Part Status: Under Review; Type: Inductor; Vendor: MURATA; Vendor Part Number: LQG15HS2N4S02D; Vendor Part Status: Active; Weight: 0.001g
L12 L13 = INDUCTOR_HOR_1_2: INDUCTOR, RF, CHIP, NON-MAGNETIC CORE, 2nH, -0.3nH/+0.3nH, 0.3A, -55DEGC/+125DEGC, 0402, SMD; Additional Datasheet URL: https://search.murata.co.jp/Ceramy/image/img/P02/JELF243B-0010.pdf; AutoDoc File: https://notefied-dynamic-precision.com/DB/Apps/Desktop/Item/Object.aspx?id=113364; BU Name: TEXAS INSTRUMENTS NORWAY; Budget Currency: EUR; Budget Price: 0.031; Budgetary Price: 0.031 EUR; Client Status: UNDER_REVIEW; Core Material: NON-MAGNETIC; Country of Origin: Japan,Singapore; Datasheet URL: https://www.murata.com/~/media/webrenewal/support/library/catalog/products/inductor/chip/o05e.ashx?la=en-gb; Datasheet URL 1: http://psearch.murata.com/inductor/product/LQG15HS2N0S02%23.pdf; Datasheet URL 2: http://www.murata.com/~/media/webrenewal/support/library/catalog/products/inductor/chip/o05e.ashx; Exclusive for Customers: TEXAS INSTRUMENTS NORWAY; Frequency: 6GHz; Lead Time: 10; Mass: 0.001g; Max Oper Temp: +125DEGC; Max Tol: +0.3nH; Maximum Operating Temperature: +125DEGC; Maximum Tolerance: +0.3nH; Min Oper Temp: -55DEGC; Min Tol: -0.3nH; Minimum Operating Temperature: -55DEGC; Minimum Tolerance: -0.3nH; Mounting Type: SMD; NOTEfied URL: https://notefied-dynamic-precision.com/NOTEfiedWebInterface/part/show?partNumber=03-07527; Notes: Standard item: Duplicate Reason: custom footprint for TEXAS INSTRUMENTS NORWAY.; PCB Package: 0402; Packing Size: 10000; Packing Type: Tape & Reel; Part Number: 03-07527; Part Type: Inductor|RF|CHIP|0402; REACH/SVHC Compliance: Compliant; REACH/SVHC Details: SVHC List Version Jul 7, 2017; REACH/SVHC Source: REACH Declaration; REACH/SVHC Status: Unaffected; REACH/SVHC_COMPLIANCE: COMPLIANT; REACH/SVHC_DETAILS: SVHC LIST VERSION Dec 17, 2015; REACH/SVHC_SOURCE: REACH DECLARATION; REACH/SVHC_STATUS: UNAFFECTED; ROHS: Compliant; Revision: R018; RoHS Status: ROHS_COMPLIANT; Rtd Current: 0.3A; Status: Released; Texas Part Status: Under Review; Type: Inductor; Vendor: MURATA; Vendor Part Number: LQG15HS2N0S02D; Vendor Part Status: Active; Weight: 0.001g
P1 P2 = CONN_HEADER_2X10_P_S: CONNECTOR, HEADER, FEMALE, STRAIGHT, 2 ROWS, 20 PINS, PITCH 1.27mm, SMD; ALT_SYMBOLS: SAMTEC_SFM11002AL,SAMTEC_SFM11002AM; Additional Datasheet URL: http://suddendocs.samtec.com/prints/sfm-1xx-xx-xxx-d-xxx-mkt.pdf; Alt IPC Footprints: SAMTEC_SFM11002AL,SAMTEC_SFM11002AM; AutoDoc File: https://notefied-dynamic-precision.com/DB/Apps/Desktop/Item/Object.aspx?id=85603; BU Name: TEXAS INSTRUMENTS NORWAY; Budget Currency: USD; Budget Price: 3.180; Budgetary Price: 5.3504 USD; CLASS: IO; Client Status: UNDER_REVIEW; Country of Origin: China,Costa Rica,Malaysia,Singapore,United States; Datasheet URL: http://suddendocs.samtec.com/catalog_english/sfm.pdf; Datasheet URL 1: http://suddendocs.samtec.com/catalog_english/sfm.pdf; Datasheet URL 2: http://suddendocs.samtec.com/prints/sfm-1xx-xx-xxx-d-xxx-mkt.pdf; Lead Time: 4; MPN: SFM-110-02-SM-D-A-K-TR; MPN Status: ACTIVE; Manufacturer: SAMTEC; Mass: 0.30875g; Max Oper Temp: +125DEGC; Maximum Operating Temperature: +125DEGC; Min Oper Temp: -55DEGC; Minimum Operating Temperature: -55DEGC; Mounting Type: SMD; NOTE Status: PREFERRED; NOTEfied URL: https://notefied-dynamic-precision.com/NOTEfiedWebInterface/part/show?partNumber=06-02251; No Of Pos: 20; No Of Rows: 2; Number of Positions: 20; Number of Rows: 2; Packing Size: 725; Packing Type: Tape & Reel; Part Number: 06-02251; Part Type: Connector|HEADER|STANDARD; Pitch: 1.27mm; REACH/SVHC Compliance: Compliant; REACH/SVHC Details: SVHC List Version Jan 12, 2017; REACH/SVHC Source: Material Declaration; REACH/SVHC Status: Unaffected; ROHS: Compliant; Revision: R013; RoHS Status: ROHS_COMPLIANT; Status: Released; Texas Part Status: Under Review; Type: Connector; Vendor: SAMTEC; Vendor Part Number: SFM-110-02-SM-D-A-K-TR; Vendor Part Status: Active; Weight: 0.30875g
R1 = RESISTOR: RESISTOR, THICK FILM, 100k, -5%/+5%, 0.063W, 50V, -55DEGC/+155DEGC, 0402, SMD; Additional Datasheet URL: N/A; AutoDoc File: https://notefied-dynamic-precision.com/DB/Apps/Desktop/Item/Object.aspx?id=114565; BU Name: TEXAS INSTRUMENTS NORWAY; Budget Currency: EUR; Budget Price: 0.014; Budgetary Price: 0.014 EUR; CLASS: DISCRETE; Client Status: UNDER_REVIEW; Country of Origin: United States; Datasheet URL: https://www.vishay.com/docs/20035/dcrcwe3.pdf; Datasheet URL 1: http://www.vishay.com/docs/20035/dcrcwe3.pdf; Datasheet URL 2: N/A; Definied Quality: INDUSTRIAL; Esd Level: N/A; Exclusive for Customers: TEXAS INSTRUMENTS NORWAY; Lead Time: 18; LifeCycle Status: ACTIVE; MPN: RESISTOR_0402_100k_+/-1%_50V_0.063W_M_+/-100PPM; MPN Status: ACTIVE; MSL: N/A; MTBF: N/A; MTBF Standard: N/A; Manufacturer: MANUFACTURER SELECTION; Mass: 0.00065g; Max Oper Temp: +155DEGC; Max TC: +200PPM/DEGC; Max Tol: +5%; Maximum Operating Temperature: +155DEGC; Maximum Temperature Coefficient: +200PPM/DEGC; Maximum Tolerance: +5%; Min Oper Temp: -55DEGC; Min TC: -200PPM/DEGC; Min Tol: -5%; Minimum Operating Temperature: -55DEGC; Minimum Temperature Coeficient: -200PPM/DEGC; Minimum Tolerance: -5%; Mounting Type: SMD; NOTE Status: PREFERRED; NOTEfied URL: https://notefied-dynamic-precision.com/NOTEfiedWebInterface/part/show?partNumber=01-22492; Notes: Standard item: Duplicate Reason: custom footprint for TEXAS INSTRUMENTS NORWAY.; Old Footprint: RESC1005X40N; PCB Package: 0402; Packing Size: 10000; Packing Type: Tape & Reel; Part Number: 01-22492; Part Type: Resistor|0402|STANDARD; REACH/SVHC Compliance: Compliant; REACH/SVHC Details: SVHC List Version Jun 20, 2016; REACH/SVHC Source: Material Declaration; REACH/SVHC Status: Unaffected; REACH/SVHC_COMPLIANCE: COMPLIANT; REACH/SVHC_DETAILS: SVHC LIST VERSION Jun 20, 2016; REACH/SVHC_SOURCE: MATERIAL DECLARATION; REACH/SVHC_STATUS: UNAFFECTED; ROHS: Exempt; Rated Current: N/A; Rated Power: 0.063W; Rated Voltage: 50V; Resistor Type: THICK FILM; Revision: R014; RoHS Status: ROHS_COMPLIANT; Rtd Current: N/A; Rtd Power: 0.063W; Rtd Voltage: 50V; Status: Released; Texas Part Status: Under Review; Type: Resistor; Vendor: VISHAY; Vendor Part Number: CRCW0402100KJNED; Vendor Part Status: Active; WEIGHT: 0.00065g
R12 = RESISTOR: RESISTOR, THICK FILM, 0, 0R/+0.02R, 0.063W, 1.5A, -55DEGC/+155DEGC, 0402, SMD; Additional Datasheet URL: N/A; AutoDoc File: https://notefied-dynamic-precision.com/DB/Apps/Desktop/Item/Object.aspx?id=114568; BU Name: TEXAS INSTRUMENTS NORWAY; Budget Currency: EUR; Budget Price: 0.007; Budgetary Price: 0.007 EUR; CLASS: DISCRETE; Client Status: UNDER_REVIEW; Country of Origin: Israel; Datasheet URL: http://www.vishay.com/docs/20035/dcrcwe3.pdf; Datasheet URL 1: http://www.vishay.com/docs/20035/dcrcwe3.pdf; Datasheet URL 2: N/A; Definied Quality: INDUSTRIAL; Esd Level: N/A; Exclusive for Customers: TEXAS INSTRUMENTS NORWAY; Lead Time: 14; LifeCycle Status: ACTIVE; MPN: RK73Z1ETTP; MPN Status: ACTIVE; MSL: 1; MTBF: N/A; MTBF Standard: N/A; Manufacturer: KOA SPEER; Mass: 0.0006152g; Max Oper Temp: +155DEGC; Max TC: N/A; Max Tol: N/A; Maximum Operating Temperature: +155DEGC; Maximum Temperature Coefficient: N/A; Maximum Tolerance: +0.02R; Min Oper Temp: -55DEGC; Min TC: N/A; Min Tol: N/A; Minimum Operating Temperature: -55DEGC; Minimum Temperature Coeficient: N/A; Minimum Tolerance: 0R; Mounting Type: SMD; NOTE Status: PREFERRED; NOTEfied URL: https://notefied-dynamic-precision.com/NOTEfiedWebInterface/part/show?partNumber=01-22495; Notes: Standard item: Duplicate Reason: custom footprint for TEXAS INSTRUMENTS NORWAY.; Old Footprint: RESC1005X40N,0402; PCB Package: 0402; Packing Size: 10000; Packing Type: Tape & Reel; Part Number: 01-22495; Part Type: Resistor|0402|JUMPER; REACH/SVHC Compliance: Compliant; REACH/SVHC Details: SVHC List Version Jul 07, 2017; REACH/SVHC Source: REACH Declaration; REACH/SVHC Status: Unaffected; REACH/SVHC_COMPLIANCE: COMPLIANT; REACH/SVHC_DETAILS: SVHC LIST VERSION Jun 20, 2016; REACH/SVHC_SOURCE: MATERIAL DECLARATION; REACH/SVHC_STATUS: UNAFFECTED; ROHS: Exempt; Rated Current: 1.5A; Rated Power: 0.063W; Rated Voltage: N/A; Resistor Type: THICK FILM; Revision: R021; RoHS Status: ROHS_COMPLIANT_WITH_EXEMPTION; Rtd Current: N/A; Rtd Power: 0.063W; Rtd Voltage: 50V; Status: Released; Texas Part Status: Under Review; Type: Resistor; Vendor: VISHAY; Vendor Part Number: CRCW04020000Z0ED; Vendor Part Status: Active; WEIGHT: 0.0006152g
U1 = IC_RF_CC2651R1F32_VQFN48: IC, MICROCONTROLLER, TEXAS INSTRUMENTS, ARM CORTEX M4F, SIMPLELINK MULTIPROTOCOL 2.4GHZ WIRELESS MCU, 1.8V TO 3.8V, VQFN48-EP, SMD; ALT_SYMBOLS: QFNFC50P700X700X100-49A2L,QFNFC50P700X700X100-49A2M; Additional Datasheet URL: N/A; Datasheet URL: https://www.ti.com/; Exclusive for Customers: TEXAS INSTRUMENTS NORWAY; Frequency: 48MHz; Mass: N/A; Maximum Operating Temperature: +105DEGC; Minimum Operating Temperature: -40DEGC; Mounting Type: SMD; NOTEfied URL: https://notefied-dynamic-precision.com/NOTEfiedWebInterface/part/show?partNumber=18-36102; Notes: Preliminary item, please check if it apperas on the website.; PCB Package: VQFN48-EP; Packing Size: N/A; Packing Type: Missing Info; Part Number: 18-36102; Part Type: IC|MICROCONTROLLER|TEXAS INSTRUMENTS; REACH/SVHC Compliance: Missing Info; REACH/SVHC Details: N/A; REACH/SVHC Source: N/A; REACH/SVHC Status: Missing Info; ROHS: Compliant; Rated Voltage: 1.8V TO 3.8V; Revision: R004; Status: Released; Texas Part Status: Under Review; Type: IC; Vendor: TEXAS INSTRUMENTS; Vendor Part Status: Preliminary
Y1 = XTAL: CRYSTAL, RESONATOR, 32.768kHz, -40DEGC/+125DEGC, SMD; ALT_SYMBOLS: XTAL_TZ1166C_A2L,XTAL_TZ1166C_A2M; Capacitance: 7pF; Datasheet URL: https://www.taisaw.com/en/product.php?pc=7; Exclusive for Customers: TEXAS INSTRUMENTS NORWAY; Maximum Operating Temperature: +125DEGC; Maximum Stability: N/A; Maximum Tolerance: +20PPM; Minimum Operating Temperature: -40DEGC; Minimum Stability: N/A; Minimum Tolerance: -20PPM; Mounting Type: SMD; NOTEfied URL: https://notefied-dynamic-precision.com/NOTEfiedWebInterface/part/show?partNumber=12-01495; Notes: Non-standard part/non-catalogue part. Created on the basis of documentation provided by the customer (Texas Instruments).; Packing Size: 3000; Packing Type: Tape & Reel; Part Number: 12-01495; Part Type: Crystal|RESONATOR; REACH/SVHC Compliance: Missing Info; REACH/SVHC Details: N/A; REACH/SVHC Source: N/A; REACH/SVHC Status: Missing Info; ROHS: Compliant; Revision: R001; Status: Released; Texas Part Status: Under Review; Type: Crystal; Vendor: TAI-SAW; Vendor Part Number: TZ1166C; Vendor Part Status: Active
Y2 = XTAL_4_V3: CRYSTAL, RESONATOR, 48MHz, -16PPM/+16PPM, -40DEGC/+105DEGC, SMD; ALT_SYMBOLS: OSCCC200X160X50-4A2L,OSCCC200X160X50-4A2M; Capacitance: 7pF; Datasheet URL: https://www.taisaw.com/en/product.php?pc=7; Exclusive for Customers: TEXAS INSTRUMENTS NORWAY; Mass: 0.0057g; Maximum Operating Temperature: +105DEGC; Maximum Stability: +16PPM; Maximum Tolerance: +8PPM; Minimum Operating Temperature: -40DEGC; Minimum Stability: -16PPM; Minimum Tolerance: -8PPM; Mounting Type: SMD; NOTEfied URL: https://notefied-dynamic-precision.com/NOTEfiedWebInterface/part/show?partNumber=12-01494; Notes: Non-standard part/non-catalogue part. Created on the basis of documentation provided by the customer (Texas Instruments).; Packing Size: 3000; Packing Type: Tape & Reel; Part Number: 12-01494; Part Type: Crystal|RESONATOR; REACH/SVHC Compliance: Missing Info; REACH/SVHC Details: N/A; REACH/SVHC Source: N/A; REACH/SVHC Status: Missing Info; ROHS: Compliant; Revision: R001; Status: Released; Texas Part Status: Under Review; Type: Crystal; Vendor: TAI-SAW; Vendor Part Number: TZ2365C; Vendor Part Status: Active
FIDU1-FIDU6 = FIDMARK: NON COMPONENT, FIDUCIAL MARK, ROUND 1mm, SMD; Additional Datasheet URL: N/A; AutoDoc File: https://notefied-dynamic-precision.com/DB/Apps/Desktop/Item/Object.aspx?id=74548; BU Name: DYNAMIC PRECISION GDANSK; CLASS: IO; Country of Origin: Missing Info; Datasheet URL: N/A; Mass: N/A; Mounting Type: SMD; NOTEfied URL: https://notefied-dynamic-precision.com/NOTEfiedWebInterface/part/show?partNumber=19-00111; Old Footprint: FID100X115; Packing Size: N/A; Packing Type: Missing Info; Part Number: 19-00111; Part Type: Non Component|FIDUCIAL; ROHS: Compliant; Revision: R015; Status: Released; Type: Non Component; Vendor: NON_COMPONENT; Vendor Part Number: FIDUCIAL_1mm; Vendor Part Status: Active
LBL1 = LABEL_Pb-free_V1: NON COMPONENT, LABEL, PB-FREE, 8mm; Additional Datasheet URL: N/A; AutoDoc File: https://notefied-dynamic-precision.com/DB/Apps/Desktop/Item/Object.aspx?id=57438; BU Name: DYNAMIC PRECISION GDANSK; Country of Origin: Missing Info; Datasheet URL: N/A; Mass: N/A; Mounting Type: Not Apply; NOTEfied URL: https://notefied-dynamic-precision.com/NOTEfiedWebInterface/part/show?partNumber=19-00159; Packing Size: N/A; Packing Type: Missing Info; Part Number: 19-00159; Part Type: Non Component|LABEL; ROHS: Missing Info; Revision: R011; Status: Released; Type: Non Component; Vendor: NON_COMPONENT; Vendor Part Status: Active
LBL2 = TI_LOGO_V1: NON COMPONENT, LABEL, TEXAS INSTRUMENTS LOGO; Additional Datasheet URL: N/A; AutoDoc File: https://notefied-dynamic-precision.com/DB/Apps/Desktop/Item/Object.aspx?id=87770; BU Name: TEXAS INSTRUMENTS NORWAY; Country of Origin: Missing Info; Datasheet URL: N/A; Exclusive for Customers: TEXAS INSTRUMENTS NORWAY; Mass: N/A; Mounting Type: Not Apply; NOTEfied URL: https://notefied-dynamic-precision.com/NOTEfiedWebInterface/part/show?partNumber=19-00350; Notes: Custom Item; Packing Size: N/A; Packing Type: Missing Info; Part Number: 19-00350; Part Type: Non Component|LABEL; ROHS: Missing Info; Revision: R014; Status: Released; Texas Part Status: Under Review; Type: Non Component; Vendor: NON_COMPONENT; Vendor Part Status: Active

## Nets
GND: A1.2(GND) A1.3(GND) C3.2 C4.2 C5.2 C6.2 C7.2 C8.2 C9.2 C13.1 C15.2 C16.2 C17.2 C18.2 C19.2 C20.2 C21.1 C31.2 J1.2 J1.3 J1.4 J1.5 P1.1 P1.19 P2.2 P2.20 U1.49(EGP) Y2.2(GND) Y2.4(GND)
VDD_EB: FL1.2 P2.7 P2.9
VDDR: C8.1 C9.1 C16.1 L1.2 U1.45(VDDR) U1.48(VDDR_RF)
VDDS: C3.1 C4.1 C5.1 C6.1 C7.1 FL1.1 R1.2 U1.13(VDDS2) U1.22(VDDS3) U1.34(VDDS_DCDC) U1.44(VDDS)
DCDC_SW: L1.1 U1.33(DCDC_SW)
DIO_0: P1.3 U1.5(DIO_0)
DIO_1: P1.5 U1.6(DIO_1)
DIO_2: P1.7 U1.7(DIO_2)
DIO_3: P1.9 U1.8(DIO_3)
DIO_4: P1.11 U1.9(DIO_4)
DIO_5: P1.13 U1.10(DIO_5)
DIO_6: P1.4 U1.11(DIO_6)
DIO_7: P1.2 U1.12(DIO_7)
DIO_8: P1.20 U1.14(DIO_8)
DIO_9: P1.18 U1.15(DIO_9)
DIO_10: P1.16 U1.16(DIO_10)
DIO_11: P1.14 U1.17(DIO_11)
DIO_12: P1.12 U1.18(DIO_12)
DIO_13: P1.15 U1.19(DIO_13)
DIO_14: P1.17 U1.20(DIO_14)
DIO_15: P1.6 U1.21(DIO_15)
DIO_16 / JTAG TDO: P2.19 U1.26(DIO_16)
DIO_17 / JTAG TDI: P2.17 U1.27(DIO_17)
DIO_18: P1.8 U1.28(DIO_18)
DIO_19: P1.10 U1.29(DIO_19)
DIO_20: P2.8 U1.30(DIO_20)
DIO_21: P2.18 U1.31(DIO_21)
DIO_22: DIO22.1 U1.32(DIO_22)
DIO_23: P2.5 U1.36(DIO_23)
DIO_24: P2.10 U1.37(DIO_24)
DIO_25: P2.11 U1.38(DIO_25)
DIO_26: P2.6 U1.39(DIO_26)
DIO_27: P2.13 U1.40(DIO_27)
DIO_28: P2.16 U1.41(DIO_28)
DIO_29: P2.14 U1.42(DIO_29)
DIO_30: P2.12 U1.43(DIO_30)
JTAG_TCK: P2.1 U1.25(JTAG_TCKC)
JTAG_TMS: P2.4 U1.24(JTAG_TMSC)
nRESET: C20.1 P2.15 R1.1 U1.35(RESET_N)
N310466: U1.47(X48M_P) Y2.1
N310868: U1.46(X48M_N) Y2.3
N314427: C21.2 L21.1 U1.2(RF_N)
N314470: C11.1 L11.1 U1.1(RF_P)
N314514: C31.1 L11.2
N314764: C11.2 L12.1 L21.2
N315193: C13.2 L12.2 L13.1
N316022: A1.1(FEED) C15.1 R12.1
N316040: C24.1 J1.1
N316649: C19.1 U1.23(DCOUPL)
N316919: C17.1 U1.3(X32K_Q1) Y1.1
N316932: C18.1 U1.4(X32K_Q2) Y1.2
N334495: C14.1 C24.2 L13.2
N356130: C14.2 R12.2

Not connected (* = marked no-connect by the designer): FIDU1 1*; FIDU2 1*; FIDU3 1*; FIDU4 1*; FIDU5 1*; FIDU6 1*; P2 3*

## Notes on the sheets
sheet 2
- Revision history:
  A0
  ---------------------------------------------------------------------------------------------
   - Based on CC26x2REM-7ID revision B0.
  - Changed C6,C8 from GRM188R60J226MEA0D to GRM188C80J226ME15D
  - Changed C11,C13,C21 from GRM1555C1H1R0CA01D to GJM1555C1H1R0CB01D
  - Changed C17,C18,C24,C31,C14 from GRM1555C1H120JA01D to GJM1555C1H120JB01D
  - Changed C19 from GRM155R61C105KA12D to GRM155C81C105KE15D
  - Changed U1 from CC2652R1FRGZR to CC2651R31T0RGZR
  - Changed Y1 from FC-135 32.7680KA-AG0 to TZ1166C
  - Changed Y2 from NX2016SA 48.000MHz EXS00A-CS05517 to TZ2365C
sheet 3
- VDDS Decoupling Capacitors
- VDDR Decoupling Capacitors
- Pin 13
- Pin 22
- Pin 44
- Pin 34
- Pin 45
- Pin 48
- Place L1 and
  C8 close to pin 33
- Mount either
  C24 or C14
  To select SMA
  or PCB ant.
  Note that a
  DC-blocking
  capacitor must
  be used if
  antenna
  has DC-path
  to ground.
- R12 and C15 for
  antenna matching
- EM connector 1
- EM connector 2
